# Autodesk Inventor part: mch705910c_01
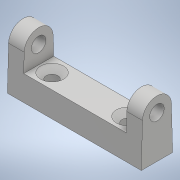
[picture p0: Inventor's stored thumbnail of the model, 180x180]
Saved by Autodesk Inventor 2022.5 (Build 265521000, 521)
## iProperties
Part Number: mch705910c_01
Material: 一般
Document SubType Name: Modeling
Designer: ImaoCorp
Density: 1 g/cm^3
Appearance: 既定
Author: ImaoCorp
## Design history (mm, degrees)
feature "mch705910c_01"
node "ソリッド1"
